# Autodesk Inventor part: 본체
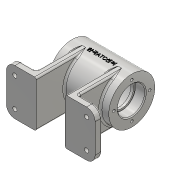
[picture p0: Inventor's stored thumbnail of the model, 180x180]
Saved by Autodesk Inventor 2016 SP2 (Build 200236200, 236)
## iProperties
Created: 2017-02
Part Number: 본체
Material: 알루미늄 6061
Document SubType Name: Modeling
Designer: H
Density: 2.7 g/cm^3
Appearance: 알루미늄 - 평지
Mass: 356.057 g
Surface Area: 423.78 cm^2
Volume: 131.873 cm^3
Author: H
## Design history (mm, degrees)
sketch "스케치1"
  geometry: L1 (0, 25.622)-(0, -36.506); L2 (52, 27)-(17, 27); L3 (17, 27)-(17, -27); L4 (17, -27)-(52, -27); L5 (52, -27)-(52, 27); L6 (0, 0)-(60.827, 0); L7 (-52, 27)-(-17, 27); L8 (-52, -27)-(-52, 27); L9 (-17, 27)-(-17, -27); L10 (-17, -27)-(-52, -27)
  constraints: 20 end point, 4 symmetric about line, 2 horizontal, 2 parallel, 1 perpendicular, 1 point on line, 1 vertical, 1 other
  dimensions: "d0" = 52 distance between parallel lines of L1 L5; "d1" = 17 distance between parallel lines of L1 L3; "d2" = 54 distance of L4.end L2.start
extrude "돌출1" new body sketch "스케치1" distance "d3" = 8; taper "d4" = 0 deg
sketch "스케치2"
  geometry: L1 (0, 27)-(0, -27) reference; C1 r 27 at (60, 0); 1 further point
  constraints: 1 centre point
  dimensions: "d5" = 54 diameter of C1; "d6" = 60 distance from line of L1 C1.centre
extrude "돌출2" join sketch "스케치2" stored distance "d7" = 70; taper "d8" = 0 deg
sketch "스케치3"
  geometry: L1 (-17, 0)-(-17, 8) reference; L2 (17, 0)-(17, 8) reference; L3 (17, 8)-(17, 60); L4 (17, 60)-(25, 60); L5 (25, 60)-(25, 8); L6 (25, 8)-(17, 8); L7 (-35, 87)-(35, 87) reference; L8 (0, 0)-(0, 87); L9 (-25, 8)-(-17, 8); L10 (-25, 60)-(-25, 8); L11 (-17, 8)-(-17, 60); L12 (-17, 60)-(-25, 60); L13 (35, 33)-(35, 87) reference; L14 (-35, 87)-(-35, 33) reference; L15 (35, 60)-(-35, 60); L16 (-17, 0)-(-52, 0) reference; L17 (-15, 92)-(-10, 92); L18 (-10, 92)-(-10, 72.116); L19 (-10, 72.116)-(-15, 72.116); L20 (-15, 72.116)-(-15, 92)
  constraints: 28 end point, 3 midpoint, 3 parallel, 3 perpendicular, 3 symmetric about line, 1 horizontal, 1 point on line, 1 vertical
  dimensions: "d9" = 8 distance of L3.end L4.end; "d13" = 92 distance between parallel lines of L16 L17; "d14" = 5 distance of L17.start L17.end; "d16" = 25 distance between parallel lines of L14 L18; "d17" = 19.88427 distance between parallel lines of L19 L17
extrude "돌출3" join sketch "스케치3" stored distance "d11" = 54; taper "d12" = 0 deg
revolve "회전1" stored, may be unused: angle "d18" = 90 deg
sketch "스케치4"
  geometry: C1 r 27 at (0, 0) reference; C2 r 16 at (0, 0); 1 further point
  constraints: 1 centre point, 1 coincident
  dimensions: "d19" = 32 diameter of C2
extrude "돌출4" cut sketch "스케치4" distance "d20" = 12; taper "d21" = 0 deg
sketch "스케치5"
  geometry: C1 r 16 at (0, 0) reference; C2 r 14 at (0, 0); 1 further point
  constraints: 1 centre point, 1 coincident
  dimensions: "d22" = 28 diameter of C2
extrude "돌출5" cut sketch "스케치5" distance "d23" = 3; taper "d24" = 0 deg
sketch "스케치6"
  geometry: C1 r 14 at (0, 0) reference; C2 r 22 at (0, 0); 1 further point
  constraints: 1 centre point, 1 coincident
  dimensions: "d25" = 44 diameter of C2
extrude "돌출6" cut sketch "스케치6" distance "d26" = 40; taper "d27" = 0 deg
sketch "스케치7"
  geometry: C1 r 27 at (0, 0) reference; C2 r 14 at (0, 0); 1 further point
  constraints: 1 centre point, 1 coincident
  dimensions: "d28" = 28 diameter of C2
extrude "돌출7" cut sketch "스케치7" distance "d29" = 3; taper "d30" = 0 deg
sketch "스케치8"
  geometry: C1 r 14 at (0, 0) reference; C2 r 16 at (0, 0); 1 further point
  constraints: 1 centre point, 1 coincident
  dimensions: "d31" = 32 diameter of C2
extrude "돌출8" cut sketch "스케치8" distance "d32" = 12; taper "d33" = 0 deg
chamfer "모따기1" distance "d34" = 1; stored, may be unused: second distance "d35" = 2, angle "d36" = 45 deg
chamfer "모따기2" distance "d37" = 1; stored, may be unused: second distance "d38" = 2, angle "d39" = 45 deg
fillet "모깎기1" dims "d40" = 3
fillet "모깎기2" dims "d41" = 0.3
sketch "스케치9" dims "d42" = 42
  geometry: L1 (0, 0)-(0, 21); C1 r 27 at (0, 0) reference; 2 further points
  constraints: 2 coincident, 2 end point, 1 vertical, 1 vertical alignment, 2 other
hole "구멍1" sketch "스케치9" at (0, 21) diameter "d43" = 3.242; stored, may be unused: countersink angle "d47" = 90 deg, drill point angle "d49" = 118 deg; dims "d44" = 8, "d45" = 4, "d46" = 2, "d48" = 10
node "작업 평면1"
fillet "모깎기3" dims "d53" = 10
sketch "스케치10" dims "d92" = 9
  geometry: L1 (42, 17)-(42, 21.5); L2 (44.598, 21.5)-(47.196, 17); L3 (47.196, 17)-(44.598, 12.5); L4 (44.598, 12.5)-(39.402, 12.5); L5 (39.402, 12.5)-(36.804, 17); L6 (36.804, 17)-(39.402, 21.5); L7 (39.402, 21.5)-(44.598, 21.5); C1 r 2.5 at (42, 17); A1 r 10 centre (42, 17) between (52, 17) and (42, 27) reference; 3 further points
  constraints: 14 end point, 4 coincident, 1 centre point, 1 midpoint, 1 vertical, 1 vertical alignment, 15 other
  dimensions: "d57" = 5 diameter of C1
extrude "돌출9" cut sketch "스케치10" distance "d55" = 3; taper "d56" = 0 deg
extrude "돌출10" cut sketch "스케치10" stored distance "d58" = 3; taper "d59" = 0 deg
sketch "스케치11"
  geometry: C1 r 5 at (0, 0) reference; 2 further points
  constraints: 1 coincident
hole "구멍2" sketch "스케치11" at (0, 0) diameter "d66" = 5.188; stored, may be unused: countersink angle "d70" = 90 deg, drill point angle "d72" = 118 deg; dims "d67" = 12, "d68" = 4, "d69" = 2, "d71" = 25
fillet "모깎기4" dims "d73" = 2
fillet "모깎기5" dims "d74" = 2
fillet "모깎기6" dims "d75" = 2
fillet "모깎기7" dims "d76" = 2
node "작업 평면2"
sketch "스케치12"
  geometry: L1 (-35, 87)-(35, 87) reference; L2 (35, 33)-(35, 87) reference; L3 (-35, 87)-(-35, 33) reference; L4 (-35, 33)-(35, 33) reference; L5 (-35, 60)-(35, 60); L6 (0, 87)-(0, 33); 3 further points
  constraints: 5 midpoint, 4 end point, 1 coincident, 1 other
feature "엠보싱1" sketch "스케치12" dims "d78" = 0.5, "d79" = 0
sketch "스케치13"
  geometry: L1 (60, 0)-(33, 0); L2 (60, 0)-(34.84, -16.339); L3 (34.84, -16.339)-(31.572, -11.307); L4 (31.572, -11.307)-(37.622, -7.378); L5 (37.622, -7.378)-(40.89, -12.41); 1 further point
  constraints: 10 end point, 2 perpendicular, 1 horizontal, 1 horizontal alignment, 1 point on line, 1 other
  dimensions: "d80" = 33 deg angle of L1 L2; "d81" = 30 distance of L1.start L2.end; "d82" = 12 diameter of L4 L2; "d93" = 7.21351 distance of L3.end L4.end
revolve "회전2" sketch "스케치13" stored, may be unused: angle "d83" = 90 deg
sketch "스케치14"
  geometry: C1 r 6 at (0, 0) reference; 2 further points
  constraints: 1 coincident
hole "구멍3" sketch "스케치14" at (0, 0) diameter "d84" = 5.188; stored, may be unused: countersink angle "d88" = 90 deg, drill point angle "d90" = 118 deg; dims "d85" = 20, "d86" = 4, "d87" = 2, "d89" = 24
fillet "모깎기8" dims "d91" = 2
node "솔리드1"
pattern_circular "원형 패턴1" dims angle "d51" = 360 deg
mirror "대칭1"
pattern_linear "직사각형 패턴1" dims "d62" = 84, "d65" = 34
node "투영된 루프1"
